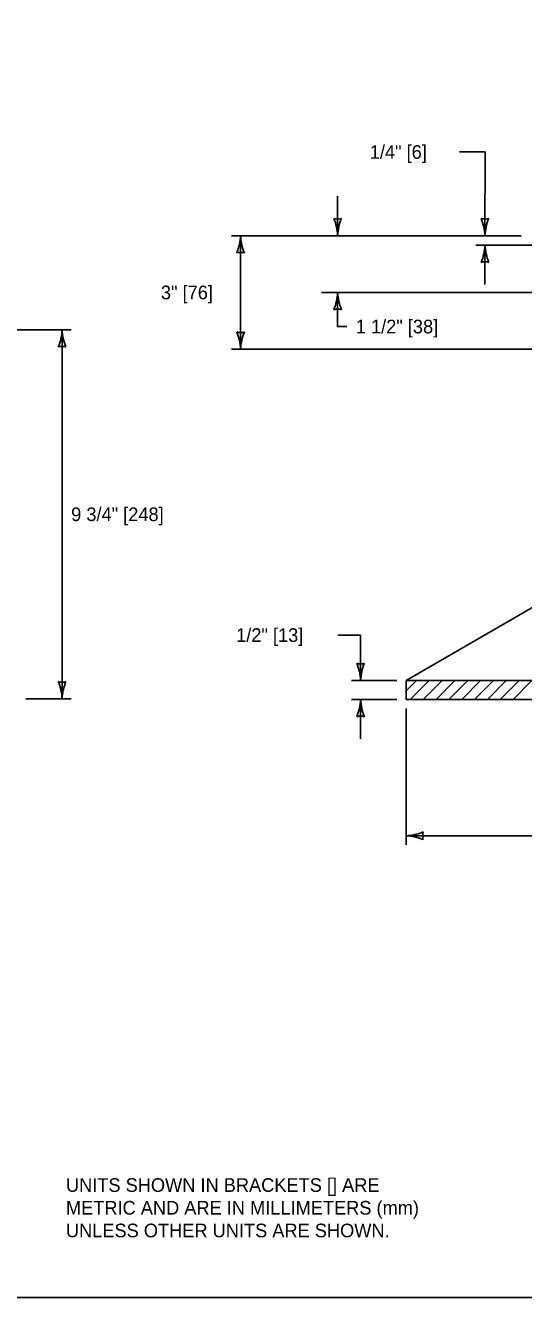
# Model space of a CAD drawing. Extents: x 49991.4 to 50021, y 49987.6 to 50011.4.
# Drawn here: x 50010.95 to 50013.15, y 49987.8 to 49993.4 of the extents above; entities that cross this region are included whole.
import ezdxf

# ---------------------------------------------------------------- set-up
doc = ezdxf.new("R2010")
doc.units = 0
for name, color, linetype in [('Level 1', 7, 'Continuous'), ('Level 2', 7, 'Continuous'), ('Level 3', 7, 'Continuous')]:
    doc.layers.add(name, color=color, linetype=linetype)

msp = doc.modelspace()

# ---------------------------------------------------------------- linework, layer by layer
at = {"layer": 'Level 1'}
for p, q in [((50012.6299, 49990.5152), (50013.2757, 49990.888)), ((50013.2757, 49990.5152), (50012.6299, 49990.5152)), ((50012.6299, 49990.5152), (50012.6299, 49990.4318)), ((50012.6299, 49990.4693), (50012.6757, 49990.5152)), ((50012.6489, 49990.4318), (50012.7323, 49990.5152)), ((50012.7055, 49990.4318), (50012.7888, 49990.5152)), ((50012.7621, 49990.4318), (50012.8454, 49990.5152)), ((50012.8186, 49990.4318), (50012.902, 49990.5152)), ((50012.8752, 49990.4318), (50012.9585, 49990.5152)), ((50012.9318, 49990.4318), (50013.0151, 49990.5152)), ((50012.9883, 49990.4318), (50013.0717, 49990.5152)), ((50013.0449, 49990.4318), (50013.1282, 49990.5152)), ((50013.1015, 49990.4318), (50013.1848, 49990.5152)), ((50012.6299, 49990.4318), (50013.359, 49990.4318))]:
    msp.add_line(p, q, dxfattribs=at)
msp.add_lwpolyline([(49999.3835, 49998.9992), (50016.7501, 49998.9992), (50016.7501, 49987.7988), (49999.3835, 49987.7988)], close=True, dxfattribs=at)
at = {"layer": 'Level 3'}
for p, q in [((50012.9781, 49992.8419), (50012.8649, 49992.8419)), ((50012.9778, 49992.4735), (50012.9781, 49992.8419)), ((50012.3287, 49992.4735), (50012.3287, 49992.6469)), ((50012.6378, 49992.4735), (50011.8609, 49992.4735)), ((50011.9009, 49992.4735), (50011.9009, 49991.9735)), ((50012.9378, 49992.4735), (50012.6378, 49992.4735)), ((50013.1378, 49992.4735), (50012.9378, 49992.4735)), ((50013.2521, 49992.4318), (50012.9378, 49992.4318)), ((50012.9778, 49992.4318), (50012.9778, 49992.2584)), ((50013.3253, 49992.2235), (50012.2577, 49992.2235)), ((50012.3287, 49992.2235), (50012.3287, 49992.0735)), ((50010.3085, 49992.0595), (50011.1144, 49992.0595)), ((50011.1144, 49990.4345), (50011.1144, 49992.0595)), ((50011.1144, 49992.0595), (50011.1544, 49992.0595)), ((50012.3287, 49992.0735), (50012.3687, 49992.0735)), ((50013.5336, 49991.9735), (50011.8609, 49991.9735)), ((50012.4299, 49990.7152), (50012.3299, 49990.7152)), ((50012.4299, 49990.5152), (50012.4299, 49990.7152)), ((50012.5899, 49990.5152), (50012.3899, 49990.5152)), ((50010.9544, 49990.4345), (50011.1544, 49990.4345)), ((50012.5899, 49990.4318), (50012.3899, 49990.4318)), ((50012.4299, 49990.4318), (50012.4299, 49990.2584)), ((50012.6299, 49990.3918), (50012.6299, 49989.7918)), ((50012.6299, 49989.8318), (50015.3925, 49989.8318))]:
    msp.add_line(p, q, dxfattribs=at)
for centre, radius, start, end in [((50012.3287, 49992.6017), 0.0548, 252.1388, 287.8612), ((50012.096, 49992.462), 0.233, 2.8273, 22.0772), ((50012.5508, 49992.4644), 0.2223, 157.456, 177.6395), ((50012.9778, 49992.6017), 0.0548, 252.1388, 287.8612), ((50012.7451, 49992.462), 0.233, 2.8273, 22.0772), ((50013.2, 49992.4644), 0.2223, 157.456, 177.6395), ((50011.6788, 49992.4827), 0.2223, 337.456, 357.6395), ((50012.1336, 49992.485), 0.233, 182.8273, 202.0772), ((50012.7557, 49992.441), 0.2223, 337.456, 357.6395), ((50013.2106, 49992.4433), 0.233, 182.8273, 202.0772), ((50011.9009, 49992.3453), 0.0548, 72.1388, 107.8612), ((50012.9778, 49992.3036), 0.0548, 72.1388, 107.8612), ((50012.1065, 49992.2327), 0.2223, 337.456, 357.6395), ((50012.5614, 49992.235), 0.233, 182.8273, 202.0772), ((50012.3287, 49992.0953), 0.0548, 72.1388, 107.8612), ((50010.8922, 49992.0687), 0.2223, 337.456, 357.6395), ((50011.3471, 49992.071), 0.233, 182.8273, 202.0772), ((50011.9009, 49992.1017), 0.0548, 252.1388, 287.8612), ((50011.6682, 49991.962), 0.233, 2.8273, 22.0772), ((50012.123, 49991.9644), 0.2223, 157.456, 177.6395), ((50011.1144, 49991.9313), 0.0548, 72.1388, 107.8612), ((50012.4299, 49990.6434), 0.0548, 252.1388, 287.8612), ((50012.1972, 49990.5037), 0.233, 2.8273, 22.0772), ((50012.652, 49990.506), 0.2223, 157.456, 177.6395), ((50011.1144, 49990.5627), 0.0548, 252.1388, 287.8612), ((50010.8817, 49990.423), 0.233, 2.8273, 22.0772), ((50011.3365, 49990.4254), 0.2223, 157.456, 177.6395), ((50012.2077, 49990.441), 0.2223, 337.456, 357.6395), ((50012.6626, 49990.4433), 0.233, 182.8273, 202.0772), ((50012.4299, 49990.3036), 0.0548, 72.1388, 107.8612), ((50012.6184, 49990.0645), 0.233, 272.8273, 292.0772), ((50012.6207, 49989.6097), 0.2223, 67.456, 87.6395), ((50012.7581, 49989.8318), 0.0548, 162.1388, 197.8612)]:
    msp.add_arc(centre, radius, start, end, dxfattribs=at)

# ---------------------------------------------------------------- texts
at = {"layer": 'Level 2'}
for s, p in [('1/4" [6]', (50012.4702, 49992.8119)), ('3" [76]', (50011.5498, 49992.1935)), ('1 1/2" [38]', (50012.4087, 49992.0435)), ('9 3/4" [248]', (50011.1544, 49991.217)), ('1/2" [13]', (50011.8813, 49990.6852)), ('UNITS SHOWN IN BRACKETS [] ARE ', (50011.1313, 49988.2641)), ('METRIC AND ARE IN MILLIMETERS (mm) ', (50011.1313, 49988.1641)), ('UNLESS OTHER UNITS ARE SHOWN.', (50011.1313, 49988.0641))]:
    msp.add_text(s, height=0.06, dxfattribs=at).set_placement(p)

doc.saveas('drawing.dxf')
